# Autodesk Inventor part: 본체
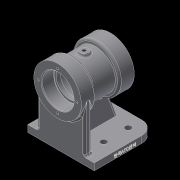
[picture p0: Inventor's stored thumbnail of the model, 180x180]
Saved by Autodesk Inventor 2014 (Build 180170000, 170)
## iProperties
Created: 2020-06
Part Number: 본체
Material: Generic
Document SubType Name: Modeling
Designer: kh
Density: 1 g/cm^3
Appearance: Default
Mass: 268.12 g
Surface Area: 653.352 cm^2
Volume: 268.12 cm^3
Author: kh
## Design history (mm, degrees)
sketch "Sketch1"
  geometry: L1 (-45, -49)-(45, -49); L2 (45, -49)-(45, 49); L3 (45, 49)-(-45, 49); L4 (-45, 49)-(-45, -49); L5 (-45, -49)-(45, 49); L6 (45, -49)-(-45, 49); 1 further point
  constraints: 12 end point, 2 midpoint, 2 parallel, 1 horizontal, 1 perpendicular
  dimensions: "d0" = 90 distance of L2.end L3.end; "d1" = 98 distance of L1.end L2.end
extrude "Extrusion1" new body sketch "Sketch1" distance "d2" = 10; taper "d3" = 0 deg
fillet "Fillet1" dims "d4" = 20
workplane "Work Plane1"
sketch "Sketch2"
  geometry: L1 (-15.944, 80)-(113.944, 80); L2 (0, 0)-(98, 0) reference; C1 r 35 at (49, 80); 3 further points
  constraints: 2 end point, 2 midpoint, 1 centre point, 1 coincident, 1 horizontal, 1 vertical alignment
  dimensions: "d6" = 80 distance between parallel lines of L2 L1; "d7" = 70 diameter of C1
extrude "Extrusion2" join sketch "Sketch2" distance "d8" = 22; taper "d9" = 0 deg
sketch "Sketch3"
  geometry: C1 r 35 at (0, 0) reference; C2 r 29 at (0, 0); 1 further point
  constraints: 1 centre point, 1 coincident
  dimensions: "d10" = 58 diameter of C2
extrude "Extrusion3" join sketch "Sketch3" distance "d11" = 34; taper "d12" = 0 deg
sketch "Sketch4"
  geometry: C1 r 29 at (0, 0) reference; C2 r 35 at (0, 0); 1 further point
  constraints: 1 centre point, 1 coincident
  dimensions: "d13" = 70 diameter of C2
extrude "Extrusion4" join sketch "Sketch4" distance "d14" = 22; taper "d15" = 0 deg
workplane "Work Plane3"
sketch "Sketch5"
  geometry: L1 (50, 35)-(50, -35) reference; L2 (11, 35)-(11, -35); C1 r 6 at (11, 0); 2 further points
  constraints: 2 end point, 1 centre point, 1 coincident, 1 horizontal alignment, 1 midpoint, 1 parallel
  dimensions: "d18" = 39 distance between parallel lines of L2 L1; "d19" = 12 diameter of C1
extrude "Extrusion5" join sketch "Sketch5" distance "d20" = 22; taper "d21" = 0 deg
sketch "Sketch6"
  geometry: C1 r 35 at (0, 0) reference; C2 r 23.5 at (0, 0); 1 further point
  constraints: 1 centre point, 1 coincident
  dimensions: "d22" = 47 diameter of C2
extrude "Extrusion6" cut sketch "Sketch6" distance "d23" = 18; taper "d24" = 0 deg
sketch "Sketch7"
  geometry: C1 r 23.5 at (0, 0) reference; C2 r 20 at (0, 0); 1 further point
  constraints: 1 centre point, 1 coincident
  dimensions: "d25" = 40 diameter of C2
extrude "Extrusion7" cut sketch "Sketch7" distance "d26" = 6; taper "d27" = 0 deg
sketch "Sketch8"
  geometry: C1 r 20 at (0, 0) reference; C2 r 23 at (0, 0); 1 further point
  constraints: 1 centre point, 1 coincident
  dimensions: "d28" = 46 diameter of C2
extrude "Extrusion8" cut sketch "Sketch8" distance "d29" = 30; taper "d30" = 0 deg
sketch "Sketch9"
  geometry: C1 r 20 at (0, 0) reference; C2 r 20 at (0, 0); 1 further point
  constraints: 1 centre point, 1 coincident
  dimensions: "d31" = 40 diameter of C2
extrude "Extrusion9" cut sketch "Sketch9" distance "d32" = 6; taper "d33" = 0 deg
sketch "Sketch10"
  geometry: C1 r 35 at (0, 0) reference; C2 r 23.5 at (0, 0); 1 further point
  constraints: 1 centre point, 1 coincident
  dimensions: "d34" = 47 diameter of C2
extrude "Extrusion10" cut sketch "Sketch10" distance "d35" = 18; taper "d36" = 0 deg
sketch "Sketch12"
  geometry: L1 (-45, 0)-(-45, 10) reference; L2 (-45, 10)-(-45, 45); L3 (-50, 45)-(-28, 45) reference; L4 (20.261, 45)-(33, 10); L5 (6, 45)-(28, 45) reference; L6 (25, 10)-(45, 10) reference; L7 (-28, 45)-(-28, 115) reference; L8 (-28, 51)-(6, 51) reference; L9 (6, 115)-(6, 45) reference; L10 (25, 10)-(-45, 10) reference; L11 (-45, 45)-(-45, 48); L12 (-45, 48)-(-30, 48); L13 (-30, 48)-(-30, 53); L14 (-30, 53)-(8, 53); L15 (8, 53)-(8, 48); L16 (20.261, 45)-(19.169, 48); L17 (8, 48)-(19.169, 48); 1 further point
  constraints: 18 end point, 4 perpendicular, 3 point on line, 2 collinear, 2 parallel
  dimensions: "d40" = 70 deg angle of L4 L6; "d41" = 12 distance of L6.end L4.end; "d106" = 3 distance between parallel lines of L3 L12; "d107" = 2 distance between parallel lines of L7 L13; "d108" = 38 distance between parallel lines of L15 L13; "d109" = 2 distance between parallel lines of L8 L14; "d110" = 3 distance between parallel lines of L5 L17
sketch "Sketch13"
  geometry: L1 (0, 0)-(0, 10) reference; L2 (14, 10)-(84, 10); L3 (14, 10)-(14, 80); L4 (84, 10)-(84, 80); A1 r 35 centre (49, 80) between (49, 45) and (14, 80) reference; 2 further points
  constraints: 6 end point, 2 perpendicular, 2 point on circle, 1 midpoint, 1 tangent, 1 vertical alignment
  dimensions: "d45" = 70 distance of L2.start L2.end
extrude "Extrusion12" join sketch "Sketch13" distance "d46" = 10; taper "d47" = 0 deg
hole "Hole1" diameter "d50" = 5.188; stored, may be unused: countersink angle "d54" = 90 deg, drill point angle "d56" = 118 deg; dims "d51" = 6, "d52" = 4, "d53" = 2, "d55" = 22, "d121" = 10, "d122" = 10
sketch "Sketch14"
  geometry: C1 r 35 at (0, 0) reference; A1 r 28.5 centre (0, 0) between (0, 28.5) and (-28.5, 0); 3 further points
  constraints: 4 point on circle, 1 centre point, 1 coincident
  dimensions: "d57" = 57 diameter of A1
hole "Hole2" sketch "Sketch14" at (0, 28.5), (-28.5, 0), (28.5, 0), (0, -28.5) diameter "d58" = 3.242; stored, may be unused: countersink angle "d62" = 90 deg, drill point angle "d64" = 118 deg; dims "d59" = 10, "d60" = 4, "d61" = 2, "d63" = 12
sketch "Sketch15"
  geometry: C1 r 35 at (0, 0) reference; A1 r 28.5 centre (0, 0) between (0, 28.5) and (-28.5, 0); 3 further points
  constraints: 4 point on circle, 1 centre point, 1 coincident
  dimensions: "d65" = 57 diameter of A1
hole "Hole3" sketch "Sketch15" at (0, 28.5), (-28.5, 0), (0, -28.5), (28.5, 0) diameter "d66" = 3.242; stored, may be unused: countersink angle "d70" = 90 deg, drill point angle "d72" = 118 deg; dims "d67" = 10, "d68" = 4, "d69" = 2, "d71" = 12
sketch "Sketch16"
  geometry: L1 (45, -29)-(45, 29) reference; L2 (-45, 49)-(-45, 35) reference; L3 (-35, 35)-(-35, -35) reference; L4 (25, 42)-(25, -38.765); L5 (-11, 35)-(-11, -33.137); L6 (0, 0)-(45, 0); L7 (-21.226, 29)-(33.964, 29); L8 (25, -29)-(-21.226, -29); A1 r 20 centre (25, -29) between (25, -49) and (45, -29) reference; A2 r 20 centre (25, 29) between (45, 29) and (25, 49) reference; 5 further points
  constraints: 10 end point, 4 parallel, 4 point on line, 2 coincident, 1 midpoint
  dimensions: "d73" = 70 distance between parallel lines of L4 L2; "d74" = 36 distance between parallel lines of L4 L5; "d75" = 29 distance between parallel lines of L6 L7
hole "Hole4" sketch "Sketch16" at (-11, 29), (25, 29), (-11, -29), (25, -29) diameter "d76" = 9; stored, may be unused: countersink angle "d80" = 90 deg, drill point angle "d82" = 118 deg; dims "d77" = 10, "d78" = 4, "d79" = 2, "d81" = 12
fillet "Fillet2" dims "d83" = 3
fillet "Fillet4" dims "d85" = 3
fillet "Fillet6" dims "d87" = 3
fillet "Fillet7" dims "d88" = 3
fillet "Fillet10" dims "d91" = 3
chamfer "Chamfer1" distance "d94" = 1; stored, may be unused: second distance "d95" = 2, angle "d96" = 45 deg
fillet "Fillet13" dims "d97" = 0.3
fillet "Fillet14" dims "d102" = 3
fillet "Fillet15" dims "d103" = 3
extrude "Extrusion16" join sketch "Sketch12" stored distance "d111" = 10; taper "d112" = 0 deg
fillet "Fillet16" dims "d113" = 3
fillet "Fillet17" dims "d114" = 3
fillet "Fillet18" dims "d115" = 3
fillet "Fillet19" dims "d116" = 3
sketch "Sketch20"
  geometry: L1 (0, 0)-(0, 10) reference; 2 further points
  constraints: 1 other
  dimensions: "d117" = 45 distance from line of point (45, 4) L1; "d118" = 4 vertical distance of L1.start point (45, 4)
emboss "Emboss1" sketch "Sketch20" dims "d9" = 0, "d119" = 0.5, "d120" = 0
workplane "Work Plane4"
sketch "Sketch21"
  geometry: C1 r 20 at (0, 0) reference; C2 r 23 at (0, 0); 1 further point
  constraints: 1 centre point, 1 coincident
  dimensions: "d124" = 46 diameter of C2
extrude "Extrusion17" cut sketch "Sketch21" stored distance "d125" = 30; taper "d126" = 0 deg
fillet "Fillet20" dims "d127" = 3
body "Solid1"
other parameters: "d5" = 5, "d17" = 112, "d123" = -39
